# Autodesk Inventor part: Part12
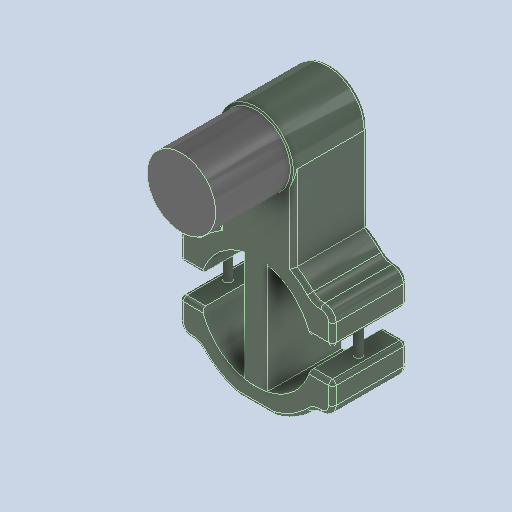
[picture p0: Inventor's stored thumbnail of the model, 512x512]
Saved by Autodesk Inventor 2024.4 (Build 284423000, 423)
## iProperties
Created: 2025-07
Part Number: Part12
Material: Generic
Document SubType Name: Modeling
Designer: AdminForWorker
Density: 1 g/cm^3
Appearance: Default
Author: AdminForWorker
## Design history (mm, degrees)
feature "Body2"
feature "Body3"
feature "Body4"
body "Solid1"
body "Solid2"
body "Solid3"
